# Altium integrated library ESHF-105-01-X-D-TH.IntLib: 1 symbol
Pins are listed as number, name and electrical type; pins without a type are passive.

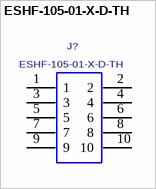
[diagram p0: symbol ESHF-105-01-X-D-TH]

## ESHF-105-01-X-D-TH
designator J?
0.05"X0.05" EXTRA LENGTH SHROUDED TERMINAL STRIP.; MANUFACTURER: SAMTEC
footprint ESHF-105-01-X-D-TH
pins: 1, 2, 3, 4, 5, 6, 7, 8, 9, 10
